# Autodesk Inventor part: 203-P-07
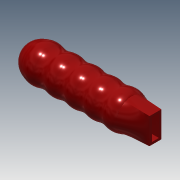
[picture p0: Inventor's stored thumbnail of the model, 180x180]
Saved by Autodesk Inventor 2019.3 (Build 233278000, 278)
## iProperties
Created: 2015-08
Part Number: 203-P-07
Material: Ogólny
Document SubType Name: Modeling
Designer: CADENGINEERING4
Density: 1 g/cm^3
Appearance: Czerwona
Author: CADENGINEERING4
Revision Number: ÈÎºÎ
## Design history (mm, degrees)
feature "Ô²½Ç2"
node "Bryła1"
